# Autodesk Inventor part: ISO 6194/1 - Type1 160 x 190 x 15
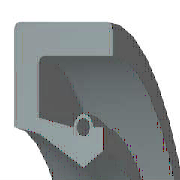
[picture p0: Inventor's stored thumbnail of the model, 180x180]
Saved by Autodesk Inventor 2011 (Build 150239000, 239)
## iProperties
Created: 2010-02
Part Number: ISO 6194/1 - Type1 160 x 190 x 15
Material: Rubber
Description: Rotary shaft lip type seals
Document SubType Name: Modeling
Standard: ISO 6194/1
Designer: 129877
Standard Revision: First edition 1982-10-01
Standards Organization: ISO
Language: en-US
Size Designation: Type1 160 x 190 x 15
Categories: <MemberInstance><Categories><Category DisplayName="Shaft Parts" InternalName="7f7aeb1f-a693-4053-b835-cee3144e0d98" Mnemonic="SHFT"><Category DisplayName="Seali
Density: 0.93 g/cm^3
Mass: 58.0467 g
Surface Area: 413.108 cm^2
Volume: 62.4158 cm^3
IsCustomPart: 0
Author: 129877
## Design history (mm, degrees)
revolve "Body" stored, may be unused: angle "d17" = 90 deg
revolve "Spring1" stored, may be unused: angle "d18" = 90 deg
body "Solid1"
sketch "Sketch1"
  geometry: L1 (0, 95)-(15, 95); L2 (15, 95)-(15, 91.75); L3 (15, 91.75)-(3.75, 91.75); L4 (0, 95)-(0, 84.5); L5 (0, 84.5)-(3.75, 83.75); L6 (3.75, 83.75)-(10.5, 80); L7 (10.5, 80)-(0, 80); L8 (13.5, 81.875)-(13.5, 84.5); L9 (0, 0)-(9.586, 0) reference; L10 (10.5, 80)-(13.5, 81.875); L11 (0, 18)-(0, -3) reference; L12 (-1.917, 0)-(11.503, 0) reference; L13 (9, 84.5)-(3.75, 85.55); L14 (3.75, 85.55)-(3.75, 91.75); L15 (13.5, 84.5)-(12, 84.5); C1 r 0.975 at (10.5, 84.5); A1 r 1.5 centre (10.5, 84.5) between (12, 84.5) and (9, 84.5)
  constraints: 26 end point, 5 horizontal alignment, 4 perpendicular, 2 centre point, 2 collinear, 2 horizontal, 2 parallel, 2 point on circle, 2 point on line, 2 vertical alignment, 1 coincident
  dimensions: "d0" = 190 diameter of L1 L9 (= SD2); "d1" = 163.75 diameter of L8.start L9 (= ABDM); "d2" = 3.25 distance of L1.end L2.end (computed from SD); "d3" = 1.95 diameter of C1 (= SPDI); "d4" = 3 diameter of A1 (= SPDA); "d5" = 160 diameter of L6.end L9 (= NND); "d6" = 167.5 diameter of L5.end L9 (= TKDM); "d7" = 169 diameter of L4.end L9 (= HLDM); "d8" = 10.5 distance from line of C1.centre L4 (= SPDST); "d9" = 13.5 distance between parallel lines of L8 L4 (= SDI); "d10" = 15 distance between parallel lines of L2 L4 (= SWDT); "d12" = 3.75 distance between parallel lines of L14 L4 (= SD)
fillet "Fillet1" dims "d11" = 1 (= RR)
other parameters: "SD2" = 190 [user parameter; used in 1 equation term], "SWDT" = 15 [user parameter; used in 1 equation term], "RR" = 1 [user parameter; used in 1 equation term], "SD" = 3.75 [user parameter; used in 2 equation terms], "NND" = 160 [user parameter; used in 1 equation term], "SPDA" = 3 [user parameter; used in 1 equation term], "SPDI" = 1.95 [user parameter; used in 1 equation term], "TKDM" = 167.5 [user parameter; used in 1 equation term], "HLDM" = 169 [user parameter; used in 1 equation term], "ABDM" = 163.75 [user parameter; used in 1 equation term], "SDI" = 13.5 [user parameter; used in 1 equation term], "SPDST" = 10.5 [user parameter; used in 1 equation term], "d13" = 0, "d14" = 0, "d15" = 0, "LAB" = 0.75 [user parameter]
